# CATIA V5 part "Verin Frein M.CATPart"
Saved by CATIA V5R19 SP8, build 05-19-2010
Part number: Verin Frein M
Bounding box of the stored display mesh (mm): x -69.981 to 69.981, y -817.991 to 73.918, z -1549.987 to -1450.015
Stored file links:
  G:\EU_thinkMotion\CFAO_2010\MMS_groupe3\MMS_groupe3\rdalborgo\rdalborgo\Verin Frein M.CATPart
  G:\EU_thinkMotion\CFAO_2010\MMS_groupe3\MMS_groupe3\rdalborgo\rdalborgo\rdalborgo.CATProduct
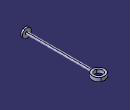
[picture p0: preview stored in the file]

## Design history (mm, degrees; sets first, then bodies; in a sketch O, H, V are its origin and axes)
Set1
  Plane1: linked copy from another document
  Point1 "B verin frein": linked copy from another document
  Line1: linked copy from another document
  Point2: linked copy from another document
  Line2: linked copy from another document
Body1 (main body)
  Sketch1 on Plane1, origin (0, 0, 0), H (0, 1, 0), V (0, 0, 1)
    point P1 (4.0096, -1500.0067)
    reference projected point E1 (4.0096, -1500.0067) from Point1
    line L1 (-41.8162, -1480.0067) -> (-65.9904, -1480.0067)
    line L2 (-65.9904, -1480.0067) -> (-65.9904, -1520.0067)
    line L3 (-65.9904, -1520.0067) -> (-41.8162, -1520.0067)
    reference projected point E2 (4.0096, -1500.0067) from Point1
    reference projected point E3 (4.0096, -1500.0067) from Point1
    arc A1 centre (4.0096, -1500.0067) radius 50 from (-41.8162, -1480.0067) to (-41.8162, -1520.0067) ccw
    distance L3 L1 = 40
    distance L3 E2 = 20
    distance L2 E3 = 70
    radius A1 = 50
    coincidence: P1 E1
    horizontal: L1 H, L3 H
    vertical: L2 V
  Shaft1: profile Sketch1, axis Line1, angle 360
  Sketch2 on Plane1, origin (0, 0, 0), H (0, 1, 0), V (0, 0, 1)
    line L1 (-55.9903, -1485.0063) -> (-797.9903, -1485.001)
    line L2 (-797.9903, -1485.001) -> (-797.9901, -1450.001)
    line L3 (-797.9901, -1450.001) -> (-817.9901, -1450.0009)
    line L4 (-817.9901, -1450.0009) -> (-817.9904, -1500.0009)
    point P5 (-817.9904, -1500.0009)
    line L5 (-817.9904, -1500.0009) -> (-55.9904, -1500.0063)
    point P6 (-55.9904, -1500.0063)
    line L6 (-55.9904, -1500.0063) -> (-55.9903, -1485.0063)
    reference projected point E1 (-817.9904, -1500.0009) from Point2
    reference projected line E2 (-1370, -1499.997) -> (0, -1500.0067) from Line2
    reference projected point E3 (4.0096, -1500.0067) from Point1
    distance L1 L5 = 15
    distance L2 L4 = 20
    distance L3 L5 = 50
    distance L6 E3 = 60
    coincidence: P5 E1, P6 E2
    perpendicularity: L1 L6, L4 L3, L3 L2, L2 L1
  Shaft2: profile Sketch2, axis Line2, angle 360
